(* Logix 5000 project; controller EVR_Heat vendor 1 type 14 code 217 rev 35.11; software revision 35.00; part 3 of 3 *)
(* tags used below, declared in another part *)
   EVR_System_Data : System;
(* MainProgram, continued *)

ROUTINE Heat_Outputs   (* ladder *)
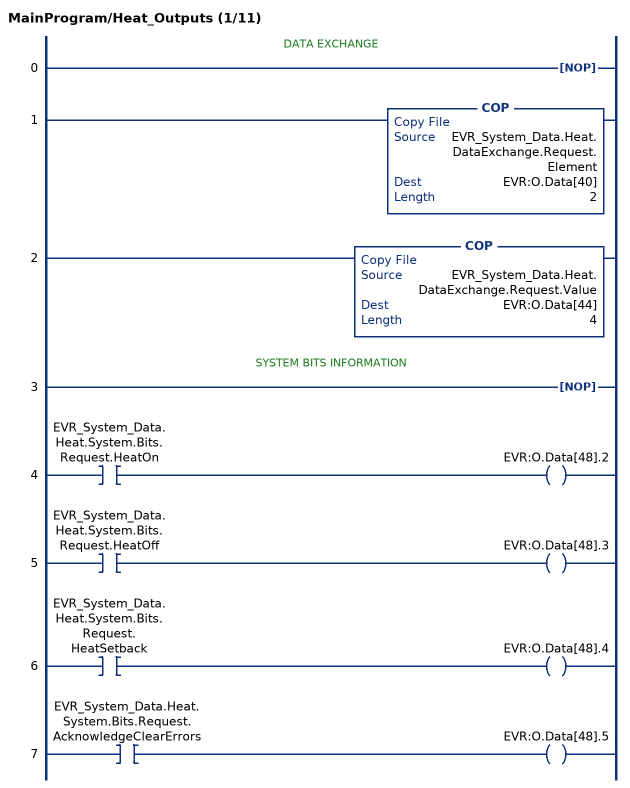
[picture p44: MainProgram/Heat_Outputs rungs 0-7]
   // DATA EXCHANGE
   0: NOP();
   1: COP(EVR_System_Data.Heat.DataExchange.Request.Element,EVR:O.Data[40],2);
   2: COP(EVR_System_Data.Heat.DataExchange.Request.Value,EVR:O.Data[44],4);
   // SYSTEM BITS INFORMATION
   3: NOP();
   4: XIC(EVR_System_Data.Heat.System.Bits.Request.HeatOn)OTE(EVR:O.Data[48].2);
   5: XIC(EVR_System_Data.Heat.System.Bits.Request.HeatOff)OTE(EVR:O.Data[48].3);
   6: XIC(EVR_System_Data.Heat.System.Bits.Request.HeatSetback)OTE(EVR:O.Data[48].4);
   7: XIC(EVR_System_Data.Heat.System.Bits.Request.AcknowledgeClearErrors)OTE(EVR:O.Data[48].5);
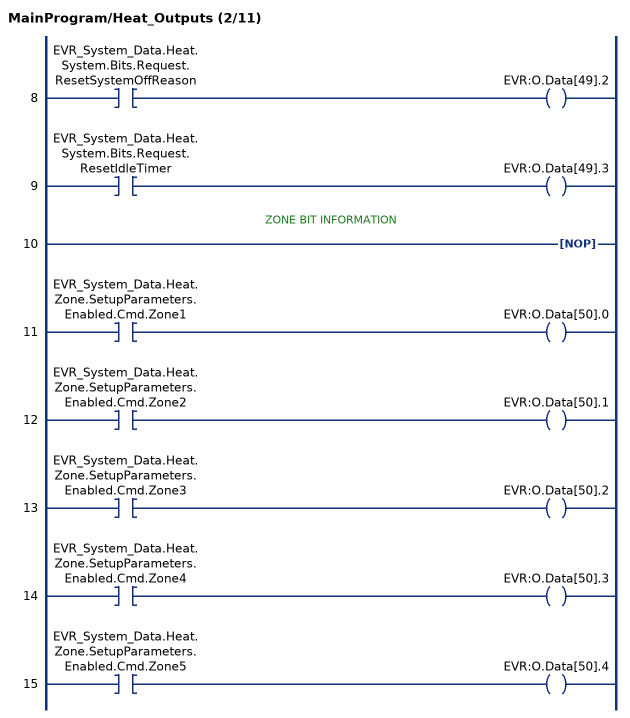
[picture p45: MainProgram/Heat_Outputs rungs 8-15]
   8: XIC(EVR_System_Data.Heat.System.Bits.Request.ResetSystemOffReason)OTE(EVR:O.Data[49].2);
   9: XIC(EVR_System_Data.Heat.System.Bits.Request.ResetIdleTimer)OTE(EVR:O.Data[49].3);
   // ZONE BIT INFORMATION
   10: NOP();
   11: XIC(EVR_System_Data.Heat.Zone.SetupParameters.Enabled.Cmd.Zone1)OTE(EVR:O.Data[50].0);
   12: XIC(EVR_System_Data.Heat.Zone.SetupParameters.Enabled.Cmd.Zone2)OTE(EVR:O.Data[50].1);
   13: XIC(EVR_System_Data.Heat.Zone.SetupParameters.Enabled.Cmd.Zone3)OTE(EVR:O.Data[50].2);
   14: XIC(EVR_System_Data.Heat.Zone.SetupParameters.Enabled.Cmd.Zone4)OTE(EVR:O.Data[50].3);
   15: XIC(EVR_System_Data.Heat.Zone.SetupParameters.Enabled.Cmd.Zone5)OTE(EVR:O.Data[50].4);
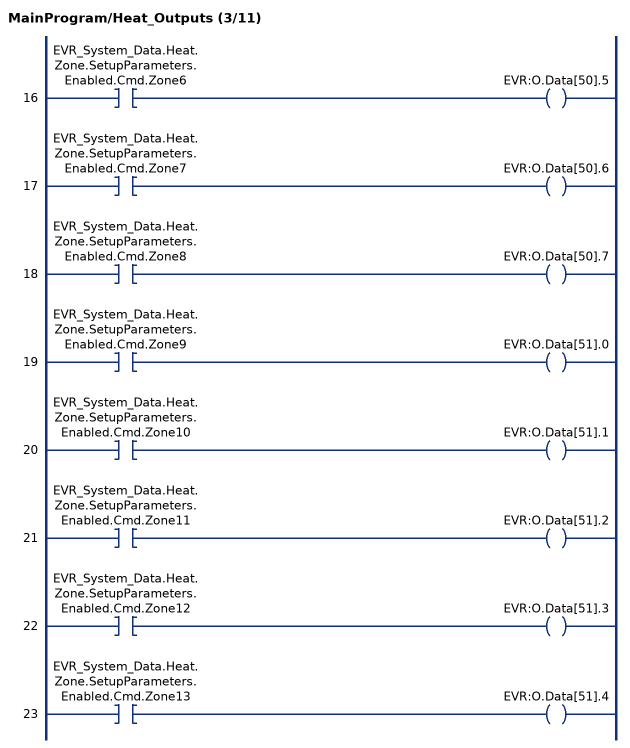
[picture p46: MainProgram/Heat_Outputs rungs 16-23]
   16: XIC(EVR_System_Data.Heat.Zone.SetupParameters.Enabled.Cmd.Zone6)OTE(EVR:O.Data[50].5);
   17: XIC(EVR_System_Data.Heat.Zone.SetupParameters.Enabled.Cmd.Zone7)OTE(EVR:O.Data[50].6);
   18: XIC(EVR_System_Data.Heat.Zone.SetupParameters.Enabled.Cmd.Zone8)OTE(EVR:O.Data[50].7);
   19: XIC(EVR_System_Data.Heat.Zone.SetupParameters.Enabled.Cmd.Zone9)OTE(EVR:O.Data[51].0);
   20: XIC(EVR_System_Data.Heat.Zone.SetupParameters.Enabled.Cmd.Zone10)OTE(EVR:O.Data[51].1);
   21: XIC(EVR_System_Data.Heat.Zone.SetupParameters.Enabled.Cmd.Zone11)OTE(EVR:O.Data[51].2);
   22: XIC(EVR_System_Data.Heat.Zone.SetupParameters.Enabled.Cmd.Zone12)OTE(EVR:O.Data[51].3);
   23: XIC(EVR_System_Data.Heat.Zone.SetupParameters.Enabled.Cmd.Zone13)OTE(EVR:O.Data[51].4);
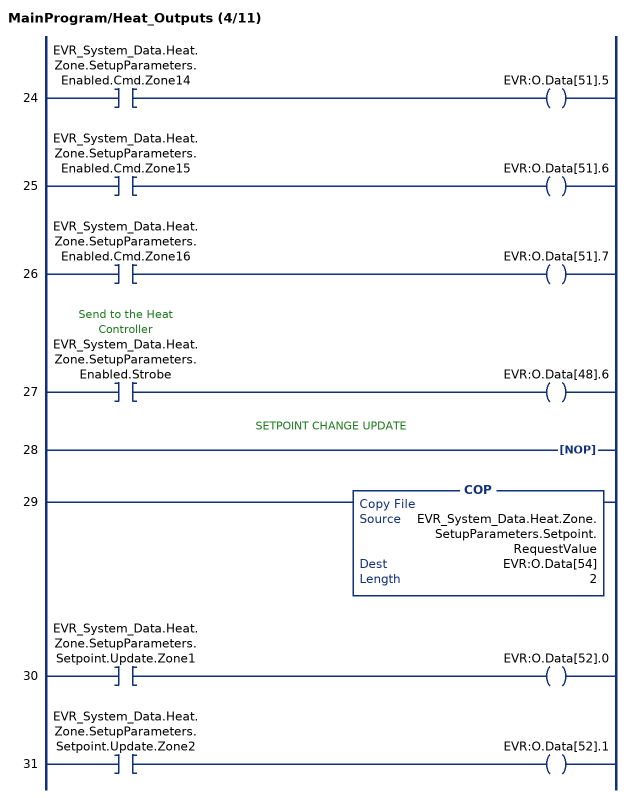
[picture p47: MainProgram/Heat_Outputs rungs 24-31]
   24: XIC(EVR_System_Data.Heat.Zone.SetupParameters.Enabled.Cmd.Zone14)OTE(EVR:O.Data[51].5);
   25: XIC(EVR_System_Data.Heat.Zone.SetupParameters.Enabled.Cmd.Zone15)OTE(EVR:O.Data[51].6);
   26: XIC(EVR_System_Data.Heat.Zone.SetupParameters.Enabled.Cmd.Zone16)OTE(EVR:O.Data[51].7);
   27: XIC(EVR_System_Data.Heat.Zone.SetupParameters.Enabled.Strobe)OTE(EVR:O.Data[48].6);
   // SETPOINT CHANGE UPDATE
   28: NOP();
   29: COP(EVR_System_Data.Heat.Zone.SetupParameters.Setpoint.RequestValue,EVR:O.Data[54],2);
   30: XIC(EVR_System_Data.Heat.Zone.SetupParameters.Setpoint.Update.Zone1)OTE(EVR:O.Data[52].0);
   31: XIC(EVR_System_Data.Heat.Zone.SetupParameters.Setpoint.Update.Zone2)OTE(EVR:O.Data[52].1);
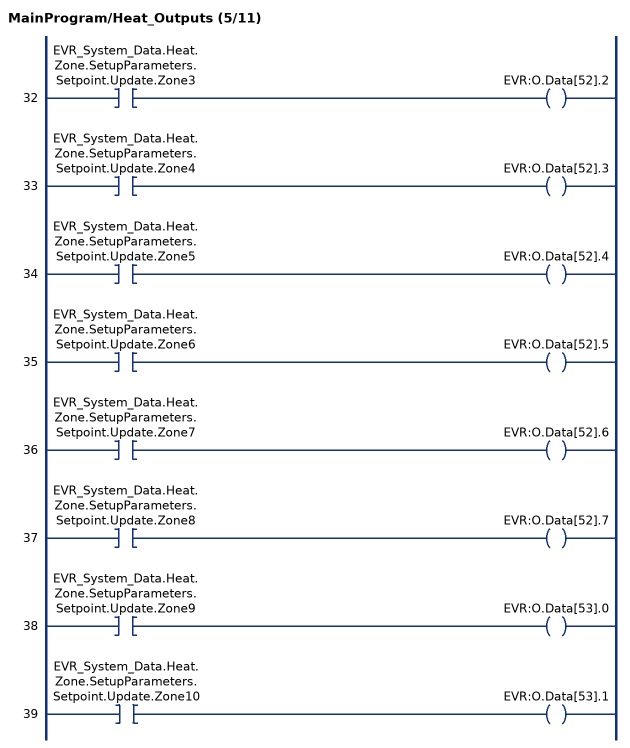
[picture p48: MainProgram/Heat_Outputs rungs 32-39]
   32: XIC(EVR_System_Data.Heat.Zone.SetupParameters.Setpoint.Update.Zone3)OTE(EVR:O.Data[52].2);
   33: XIC(EVR_System_Data.Heat.Zone.SetupParameters.Setpoint.Update.Zone4)OTE(EVR:O.Data[52].3);
   34: XIC(EVR_System_Data.Heat.Zone.SetupParameters.Setpoint.Update.Zone5)OTE(EVR:O.Data[52].4);
   35: XIC(EVR_System_Data.Heat.Zone.SetupParameters.Setpoint.Update.Zone6)OTE(EVR:O.Data[52].5);
   36: XIC(EVR_System_Data.Heat.Zone.SetupParameters.Setpoint.Update.Zone7)OTE(EVR:O.Data[52].6);
   37: XIC(EVR_System_Data.Heat.Zone.SetupParameters.Setpoint.Update.Zone8)OTE(EVR:O.Data[52].7);
   38: XIC(EVR_System_Data.Heat.Zone.SetupParameters.Setpoint.Update.Zone9)OTE(EVR:O.Data[53].0);
   39: XIC(EVR_System_Data.Heat.Zone.SetupParameters.Setpoint.Update.Zone10)OTE(EVR:O.Data[53].1);
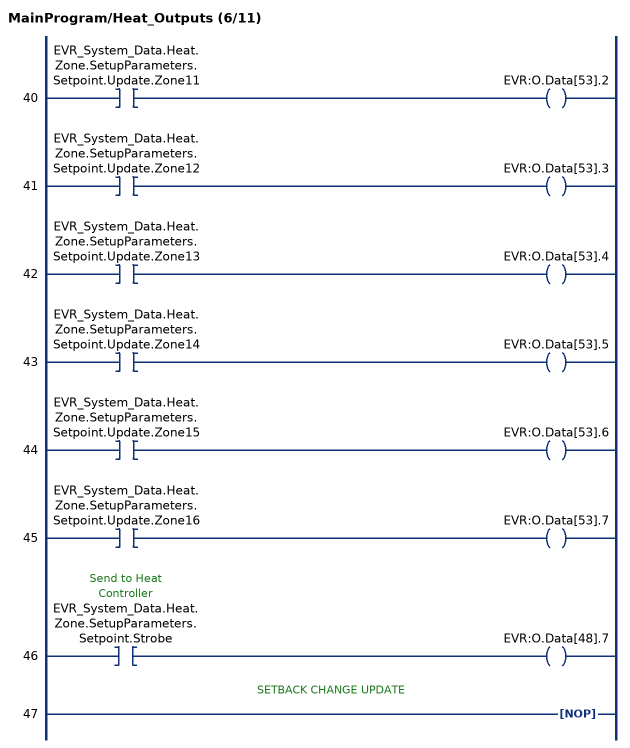
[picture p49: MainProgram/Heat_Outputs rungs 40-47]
   40: XIC(EVR_System_Data.Heat.Zone.SetupParameters.Setpoint.Update.Zone11)OTE(EVR:O.Data[53].2);
   41: XIC(EVR_System_Data.Heat.Zone.SetupParameters.Setpoint.Update.Zone12)OTE(EVR:O.Data[53].3);
   42: XIC(EVR_System_Data.Heat.Zone.SetupParameters.Setpoint.Update.Zone13)OTE(EVR:O.Data[53].4);
   43: XIC(EVR_System_Data.Heat.Zone.SetupParameters.Setpoint.Update.Zone14)OTE(EVR:O.Data[53].5);
   44: XIC(EVR_System_Data.Heat.Zone.SetupParameters.Setpoint.Update.Zone15)OTE(EVR:O.Data[53].6);
   45: XIC(EVR_System_Data.Heat.Zone.SetupParameters.Setpoint.Update.Zone16)OTE(EVR:O.Data[53].7);
   46: XIC(EVR_System_Data.Heat.Zone.SetupParameters.Setpoint.Strobe)OTE(EVR:O.Data[48].7);
   // SETBACK CHANGE UPDATE
   47: NOP();
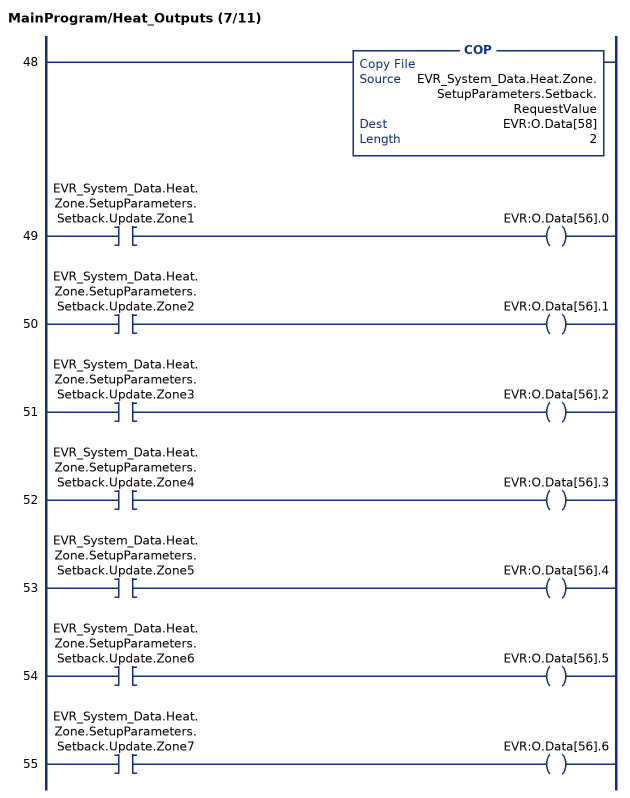
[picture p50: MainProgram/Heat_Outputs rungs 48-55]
   48: COP(EVR_System_Data.Heat.Zone.SetupParameters.Setback.RequestValue,EVR:O.Data[58],2);
   49: XIC(EVR_System_Data.Heat.Zone.SetupParameters.Setback.Update.Zone1)OTE(EVR:O.Data[56].0);
   50: XIC(EVR_System_Data.Heat.Zone.SetupParameters.Setback.Update.Zone2)OTE(EVR:O.Data[56].1);
   51: XIC(EVR_System_Data.Heat.Zone.SetupParameters.Setback.Update.Zone3)OTE(EVR:O.Data[56].2);
   52: XIC(EVR_System_Data.Heat.Zone.SetupParameters.Setback.Update.Zone4)OTE(EVR:O.Data[56].3);
   53: XIC(EVR_System_Data.Heat.Zone.SetupParameters.Setback.Update.Zone5)OTE(EVR:O.Data[56].4);
   54: XIC(EVR_System_Data.Heat.Zone.SetupParameters.Setback.Update.Zone6)OTE(EVR:O.Data[56].5);
   55: XIC(EVR_System_Data.Heat.Zone.SetupParameters.Setback.Update.Zone7)OTE(EVR:O.Data[56].6);
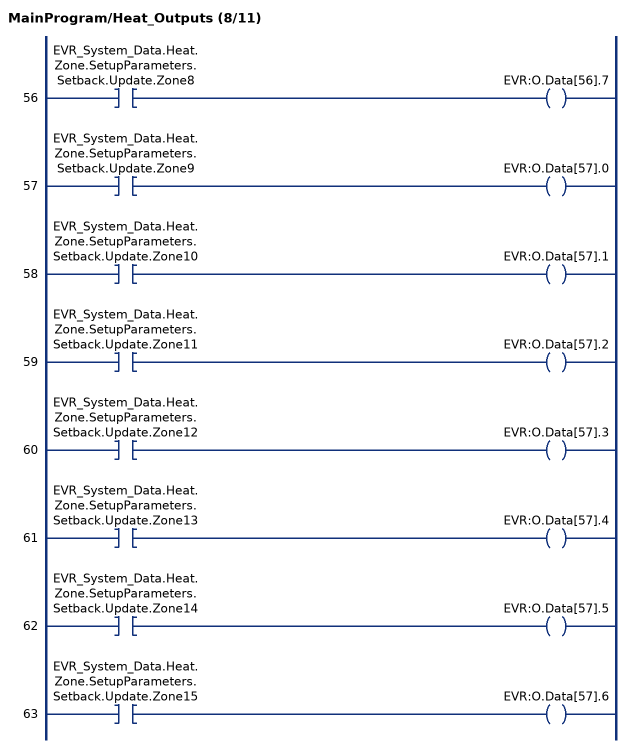
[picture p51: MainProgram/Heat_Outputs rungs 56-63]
   56: XIC(EVR_System_Data.Heat.Zone.SetupParameters.Setback.Update.Zone8)OTE(EVR:O.Data[56].7);
   57: XIC(EVR_System_Data.Heat.Zone.SetupParameters.Setback.Update.Zone9)OTE(EVR:O.Data[57].0);
   58: XIC(EVR_System_Data.Heat.Zone.SetupParameters.Setback.Update.Zone10)OTE(EVR:O.Data[57].1);
   59: XIC(EVR_System_Data.Heat.Zone.SetupParameters.Setback.Update.Zone11)OTE(EVR:O.Data[57].2);
   60: XIC(EVR_System_Data.Heat.Zone.SetupParameters.Setback.Update.Zone12)OTE(EVR:O.Data[57].3);
   61: XIC(EVR_System_Data.Heat.Zone.SetupParameters.Setback.Update.Zone13)OTE(EVR:O.Data[57].4);
   62: XIC(EVR_System_Data.Heat.Zone.SetupParameters.Setback.Update.Zone14)OTE(EVR:O.Data[57].5);
   63: XIC(EVR_System_Data.Heat.Zone.SetupParameters.Setback.Update.Zone15)OTE(EVR:O.Data[57].6);
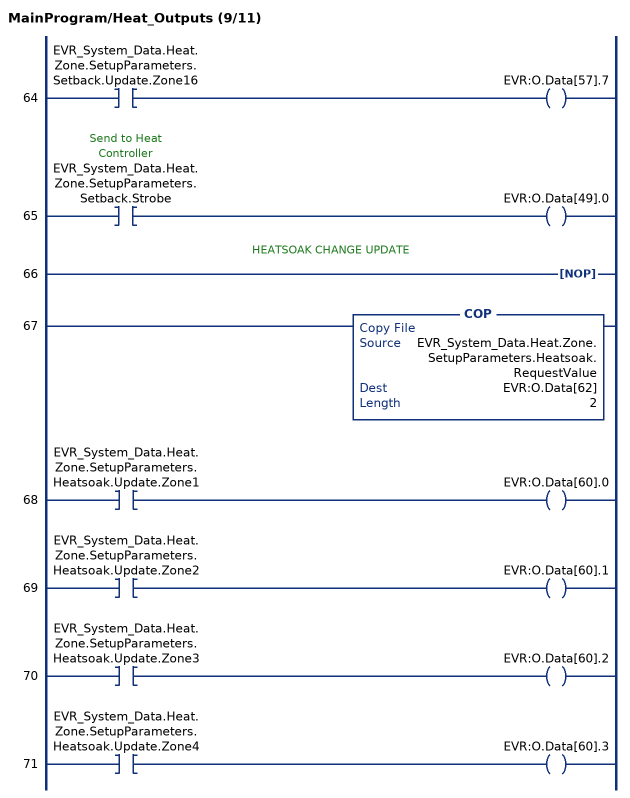
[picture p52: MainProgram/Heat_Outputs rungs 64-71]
   64: XIC(EVR_System_Data.Heat.Zone.SetupParameters.Setback.Update.Zone16)OTE(EVR:O.Data[57].7);
   65: XIC(EVR_System_Data.Heat.Zone.SetupParameters.Setback.Strobe)OTE(EVR:O.Data[49].0);
   // HEATSOAK CHANGE UPDATE
   66: NOP();
   67: COP(EVR_System_Data.Heat.Zone.SetupParameters.Heatsoak.RequestValue,EVR:O.Data[62],2);
   68: XIC(EVR_System_Data.Heat.Zone.SetupParameters.Heatsoak.Update.Zone1)OTE(EVR:O.Data[60].0);
   69: XIC(EVR_System_Data.Heat.Zone.SetupParameters.Heatsoak.Update.Zone2)OTE(EVR:O.Data[60].1);
   70: XIC(EVR_System_Data.Heat.Zone.SetupParameters.Heatsoak.Update.Zone3)OTE(EVR:O.Data[60].2);
   71: XIC(EVR_System_Data.Heat.Zone.SetupParameters.Heatsoak.Update.Zone4)OTE(EVR:O.Data[60].3);
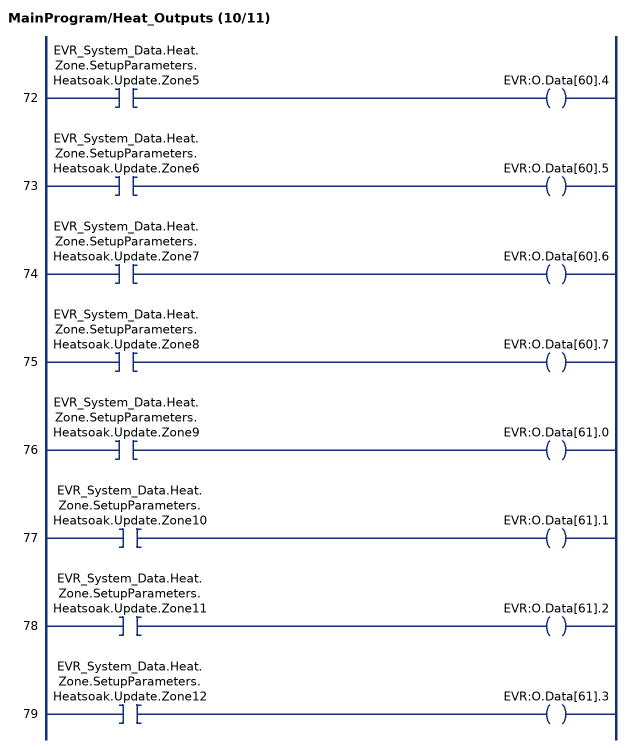
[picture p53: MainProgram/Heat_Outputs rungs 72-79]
   72: XIC(EVR_System_Data.Heat.Zone.SetupParameters.Heatsoak.Update.Zone5)OTE(EVR:O.Data[60].4);
   73: XIC(EVR_System_Data.Heat.Zone.SetupParameters.Heatsoak.Update.Zone6)OTE(EVR:O.Data[60].5);
   74: XIC(EVR_System_Data.Heat.Zone.SetupParameters.Heatsoak.Update.Zone7)OTE(EVR:O.Data[60].6);
   75: XIC(EVR_System_Data.Heat.Zone.SetupParameters.Heatsoak.Update.Zone8)OTE(EVR:O.Data[60].7);
   76: XIC(EVR_System_Data.Heat.Zone.SetupParameters.Heatsoak.Update.Zone9)OTE(EVR:O.Data[61].0);
   77: XIC(EVR_System_Data.Heat.Zone.SetupParameters.Heatsoak.Update.Zone10)OTE(EVR:O.Data[61].1);
   78: XIC(EVR_System_Data.Heat.Zone.SetupParameters.Heatsoak.Update.Zone11)OTE(EVR:O.Data[61].2);
   79: XIC(EVR_System_Data.Heat.Zone.SetupParameters.Heatsoak.Update.Zone12)OTE(EVR:O.Data[61].3);
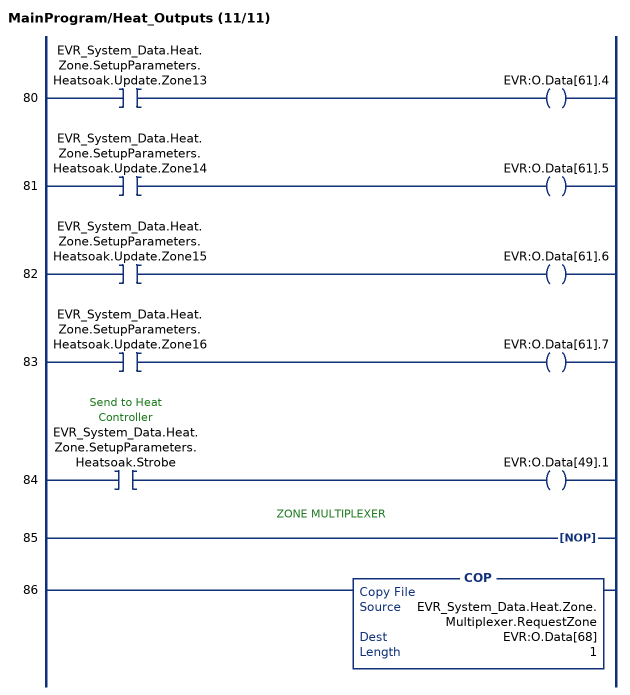
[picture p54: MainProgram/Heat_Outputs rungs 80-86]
   80: XIC(EVR_System_Data.Heat.Zone.SetupParameters.Heatsoak.Update.Zone13)OTE(EVR:O.Data[61].4);
   81: XIC(EVR_System_Data.Heat.Zone.SetupParameters.Heatsoak.Update.Zone14)OTE(EVR:O.Data[61].5);
   82: XIC(EVR_System_Data.Heat.Zone.SetupParameters.Heatsoak.Update.Zone15)OTE(EVR:O.Data[61].6);
   83: XIC(EVR_System_Data.Heat.Zone.SetupParameters.Heatsoak.Update.Zone16)OTE(EVR:O.Data[61].7);
   84: XIC(EVR_System_Data.Heat.Zone.SetupParameters.Heatsoak.Strobe)OTE(EVR:O.Data[49].1);
   // ZONE MULTIPLEXER
   85: NOP();
   86: COP(EVR_System_Data.Heat.Zone.Multiplexer.RequestZone,EVR:O.Data[68],1);
END_ROUTINE

ROUTINE MainRoutine   (* ladder *)
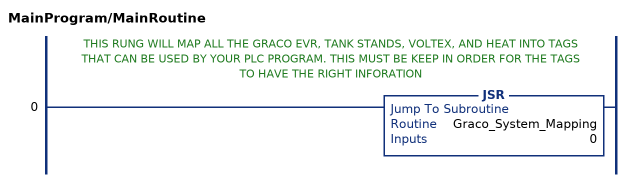
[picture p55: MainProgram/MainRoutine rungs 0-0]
   // THIS RUNG WILL MAP ALL THE GRACO EVR, TANK STANDS, VOLTEX, AND HEAT INTO TAGS THAT CAN BE USED BY YOUR PLC PROGRAM. THIS MUST BE KEEP IN ORDER FOR THE TAGS TO HAVE THE RIGHT INFORATION
   0: JSR(Graco_System_Mapping,0);
END_ROUTINE
END_PROGRAM
